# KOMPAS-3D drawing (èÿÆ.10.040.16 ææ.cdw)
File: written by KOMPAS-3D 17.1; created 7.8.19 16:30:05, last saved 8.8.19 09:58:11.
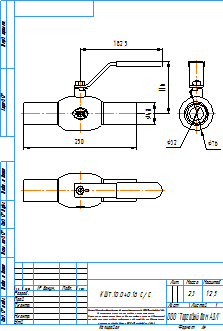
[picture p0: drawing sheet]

Sheet 1: A4, portrait

Title block, sheet 1: name: КШТ.10.040.16 С/С; material: Сталь 20  ГОСТ 1050-2013; mass: 2,3; sheets: 1; sheet format: A4; stored path: C:\Users\kka\KOMPAS_Work\Модели кранов для исследований\DN65\КШТ.10.065.16 СС.cdw

Views: Вид 1, Проекционный вид 2, Проекционный вид 3
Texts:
  kka
  adl
  Рама для чертежей
  Лит-Масса-Масштаб
  Материал-Предприятие
  Масштаб
  Изм.
  Лист
  № докум.
  Подп.
  Дата
  Лит.
  Разраб.
  Пров.
  Т.контр.
  Листов
  Внимание! Данный продукт является объектом авторского права ООО «Торговый Дом АДЛ».
  Запрещается изменение, копирование, распространение
  (в том числе путем копирования на другие сайты и ресурсы в Интернете)
  или любое иное использование информации и объектов без предварительного
  согласия правообладателя (ООО «Торговый Дом АДЛ»).
  Н.контр.
  Утв.
  ООО "Торговый дом АДЛ"
  Изменение
  Номер документа
  Подпись
  Обозначение документа
  Наименование изделия
  Масса изделия по ГОСТ 2.109-73
  Порядковый номер листа
  Общее количество листов в документе
  Характер работы, выполненной лицом, подписавшим документ
  Наименование или индекс предприятия, выпускающего документ
  Инв. № подл.
  Подп. и дата
  Взам. инв. №
  Инв. № дубл.
  Инвентарный номер подлинника по ГОСТ 2.501-68
  Подпись принявшего подлинник в отдел технической документации
  Инвентарный номер подлинника, взамен которого выпущен данный подлинник
  Инвентарный номер дубликата по ГОСТ 2.502-68
  Подпись принявшего дубликат в отдел технической документации
  Справ. №
  Перв. примен.
  Обозначение документа, взамен или на основании которого выпущен данный документ
  Обозначение документа, в котором впервые записан данный документ
  Подпись лица, копировавшего чертеж
  Обозначение формата листа
  !Рама для чертежа
Dimensions and other numbers on the sheet: 250; 116; 182,5; 48; 76; 32; 1:2,5; 1; 2,3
